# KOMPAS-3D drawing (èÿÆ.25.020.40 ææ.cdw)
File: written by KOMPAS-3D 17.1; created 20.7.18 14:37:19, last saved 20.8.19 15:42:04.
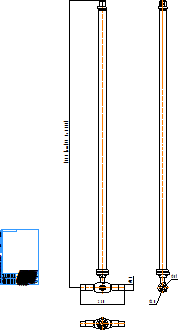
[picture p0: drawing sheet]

Sheet 1: A4, portrait

Title block, sheet 1: name: КШТ.25.020.40 С/С; sheets: 1; sheet format: A4; stored path: C:\Users\kka\KOMPAS_Work\Модели кранов для исследований\DN32\С удлинением\КШТ.22.032.40 СС.cdw

Views: Вид 1, Проекционный вид 2, Проекционный вид 3
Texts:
  kka
  adl
  (от 199 до 5000)
  Рама для чертежей
  Лит-Масса-Масштаб
  Материал-Предприятие
  Масштаб
  Изм.
  Лист
  № докум.
  Подп.
  Дата
  Лит.
  Разраб.
  Пров.
  Т.контр.
  Листов
  Внимание! Данный продукт является объектом авторского права ООО «Торговый Дом АДЛ».
  Запрещается изменение, копирование, распространение
  (в том числе путем копирования на другие сайты и ресурсы в Интернете)
  или любое иное использование информации и объектов без предварительного
  согласия правообладателя (ООО «Торговый Дом АДЛ»).
  Н.контр.
  Утв.
  ООО "Торговый дом АДЛ"
  Изменение
  Номер документа
  Подпись
  Обозначение документа
  Наименование изделия
  Масса изделия по ГОСТ 2.109-73
  Порядковый номер листа
  Общее количество листов в документе
  Характер работы, выполненной лицом, подписавшим документ
  Наименование или индекс предприятия, выпускающего документ
  Инв. № подл.
  Подп. и дата
  Взам. инв. №
  Инв. № дубл.
  Инвентарный номер подлинника по ГОСТ 2.501-68
  Подпись принявшего подлинник в отдел технической документации
  Инвентарный номер подлинника, взамен которого выпущен данный подлинник
  Инвентарный номер дубликата по ГОСТ 2.502-68
  Подпись принявшего дубликат в отдел технической документации
  Справ. №
  Перв. примен.
  Обозначение документа, взамен или на основании которого выпущен данный документ
  Обозначение документа, в котором впервые записан данный документ
  Подпись лица, копировавшего чертеж
  Обозначение формата листа
  !Рама для чертежа
Dimensions and other numbers on the sheet: 1500; 230; 28; 51; 20; 1:1; 1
